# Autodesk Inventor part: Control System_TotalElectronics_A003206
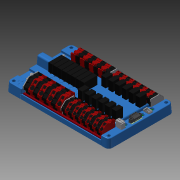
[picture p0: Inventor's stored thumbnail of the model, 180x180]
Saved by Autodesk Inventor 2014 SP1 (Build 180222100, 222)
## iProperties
Category: Control System
Company: Autodesk, Inc.
Created: 2012-11
Part Number: Control System_TotalElectronics_A003206
Document SubType Name: Modeling
Density: 1.35326 g/cm^3
Vendor: Total Electronics
Description: Power Distribution
Project: FIRST
Catalog Web Link: http://www.andymark.com/product-p/am-0865.htm
Material: Generic
Appearance: Default
Mass: 725.748 g
Surface Area: 3232.29 cm^2
Volume: 536.295 cm^3
Title: Power Distribution
Author: Autodesk, Inc.
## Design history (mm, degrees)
derived "PD Rev3 Assembly.iam"
body "Solid1"
node "PD Rev3 Bottom.ipt:1"
node "CTF040V8.iam:1::CTF040V8_1.ipt:1"
node "CTF040V8.iam:1::CTF040V8_2.ipt:1"
node "CTF040V8.iam:1::CTF040V8_3.ipt:1"
node "PD Rev3 PCB.iam:1::PD Rev3 Board.ipt:1"
node "PD Rev3 PCB.iam:1::Wago 745-831 (32A) Block.iam:1::Wago 745-"
node "PD Rev3 PCB.iam:1::Wago 745-831 (32A) Block.iam:1::Wago 745-"
node "PD Rev3 PCB.iam:1::Wago 745-831 (32A) Block.iam:1::Wago 745-"
node "PD Rev3 PCB.iam:1::Wago 745-831 (32A) Block.iam:1::Wago 745-"
node "PD Rev3 PCB.iam:1::Wago 745-831 (32A) Block.iam:1::Wago 745-"
node "PD Rev3 PCB.iam:1::Wago 745-831 (32A) Block.iam:1::Wago 745-"
node "PD Rev3 PCB.iam:1::Wago 745-831 (32A) Block.iam:1::Wago 745-"
node "PD Rev3 PCB.iam:1::Wago 745-831 (32A) Block.iam:1::Wago 745-"
node "PD Rev3 PCB.iam:1::Wago 745-831 (32A) Block.iam:1::Wago 745-"
node "PD Rev3 PCB.iam:1::Wago 745-831 (32A) Block.iam:1::Wago 745-"
node "PD Rev3 PCB.iam:1::Wago 745-831 (32A) Block.iam:1::Wago 745-"
node "PD Rev3 PCB.iam:1::Wago 745-831 (32A) Block.iam:1::Wago 745-"
node "PD Rev3 PCB.iam:1::Wago 745-831 (32A) Block.iam:1::745-300:1"
node "PD Rev3 PCB.iam:1::Wago 745-831 (32A) Block.iam:2::Wago 745-"
node "PD Rev3 PCB.iam:1::Wago 745-831 (32A) Block.iam:2::Wago 745-"
node "PD Rev3 PCB.iam:1::Wago 745-831 (32A) Block.iam:2::Wago 745-"
node "PD Rev3 PCB.iam:1::Wago 745-831 (32A) Block.iam:2::Wago 745-"
node "PD Rev3 PCB.iam:1::Wago 745-831 (32A) Block.iam:2::Wago 745-"
node "PD Rev3 PCB.iam:1::Wago 745-831 (32A) Block.iam:2::Wago 745-"
node "PD Rev3 PCB.iam:1::Wago 745-831 (32A) Block.iam:2::Wago 745-"
node "PD Rev3 PCB.iam:1::Wago 745-831 (32A) Block.iam:2::Wago 745-"
node "PD Rev3 PCB.iam:1::Wago 745-831 (32A) Block.iam:2::Wago 745-"
node "PD Rev3 PCB.iam:1::Wago 745-831 (32A) Block.iam:2::Wago 745-"
node "PD Rev3 PCB.iam:1::Wago 745-831 (32A) Block.iam:2::Wago 745-"
node "PD Rev3 PCB.iam:1::Wago 745-831 (32A) Block.iam:2::Wago 745-"
node "PD Rev3 PCB.iam:1::Wago 745-831 (32A) Block.iam:2::745-300:1"
node "PD Rev3 PCB.iam:1::Wago 745-851 (76A) Block.iam:1::Wago 745-"
node "PD Rev3 PCB.iam:1::Wago 745-851 (76A) Block.iam:1::Wago 745-"
node "PD Rev3 PCB.iam:1::Wago 745-851 (76A) Block.iam:1::Wago 745-"
node "PD Rev3 PCB.iam:1::Wago 745-851 (76A) Block.iam:1::Wago 745-"
node "PD Rev3 PCB.iam:1::Wago 745-851 (76A) Block.iam:1::Wago 745-"
node "PD Rev3 PCB.iam:1::Wago 745-851 (76A) Block.iam:1::Wago 745-"
node "PD Rev3 PCB.iam:1::Wago 745-851 (76A) Block.iam:1::Wago 745-"
node "PD Rev3 PCB.iam:1::Wago 745-851 (76A) Block.iam:1::Wago 745-"
node "PD Rev3 PCB.iam:1::Wago 745-851 (76A) Block.iam:1::745-500:1"
node "PD Rev3 PCB.iam:1::Wago 745-851 (76A) Block.iam:2::Wago 745-"
node "PD Rev3 PCB.iam:1::Wago 745-851 (76A) Block.iam:2::Wago 745-"
node "PD Rev3 PCB.iam:1::Wago 745-851 (76A) Block.iam:2::Wago 745-"
node "PD Rev3 PCB.iam:1::Wago 745-851 (76A) Block.iam:2::Wago 745-"
node "PD Rev3 PCB.iam:1::Wago 745-851 (76A) Block.iam:2::Wago 745-"
node "PD Rev3 PCB.iam:1::Wago 745-851 (76A) Block.iam:2::Wago 745-"
node "PD Rev3 PCB.iam:1::Wago 745-851 (76A) Block.iam:2::Wago 745-"
node "PD Rev3 PCB.iam:1::Wago 745-851 (76A) Block.iam:2::Wago 745-"
node "PD Rev3 PCB.iam:1::Wago 745-851 (76A) Block.iam:2::745-500:1"
node "PD Rev3 PCB.iam:1::LED.ipt:1"
node "PD Rev3 PCB.iam:1::LED.ipt:2"
node "PD Rev3 PCB.iam:1::734-132:1"
node "PD Rev3 PCB.iam:1::LED.ipt:3"
node "PD Rev3 PCB.iam:1::Wurth Lug.ipt:1"
node "PD Rev3 PCB.iam:1::Wurth Lug.ipt:2"
node "PD Rev3 PCB.iam:1::Big CB in Holder.ipt:1"
node "PD Rev3 PCB.iam:1::Big CB in Holder.ipt:2"
node "PD Rev3 PCB.iam:1::Big CB in Holder.ipt:3"
node "PD Rev3 PCB.iam:1::Big CB in Holder.ipt:4"
node "PD Rev3 PCB.iam:1::Big CB in Holder.ipt:5"
node "PD Rev3 PCB.iam:1::Big CB in Holder.ipt:6"
node "PD Rev3 PCB.iam:1::Big CB in Holder.ipt:7"
node "PD Rev3 PCB.iam:1::Big CB in Holder.ipt:8"
node "PD Rev3 PCB.iam:1::Medium CB in Holder.ipt:2"
node "PD Rev3 PCB.iam:1::Medium CB in Holder.ipt:1"
node "PD Rev3 PCB.iam:1::Medium CB in Holder.ipt:3"
node "PD Rev3 PCB.iam:1::Medium CB in Holder.ipt:4"
node "PD Rev3 PCB.iam:1::Medium CB in Holder.ipt:5"
node "PD Rev3 PCB.iam:1::Medium CB in Holder.ipt:6"
node "PD Rev3 PCB.iam:1::Medium CB in Holder.ipt:7"
node "PD Rev3 PCB.iam:1::Medium CB in Holder.ipt:8"
node "PD Rev3 PCB.iam:1::Medium CB in Holder.ipt:9"
node "PD Rev3 PCB.iam:1::Medium CB in Holder.ipt:10"
node "PD Rev3 PCB.iam:1::Medium CB in Holder.ipt:11"
node "PD Rev3 PCB.iam:1::Medium CB in Holder.ipt:12"
node "PD Rev3 PCB.iam:1::739-302:1"
node "PD Rev3 PCB.iam:1::CTM040V8.ipt:1"
node "PD Rev3 Top.ipt:1"
node "734-102:1"
node "PD Rev3 Assembly.iam_Bodies"
